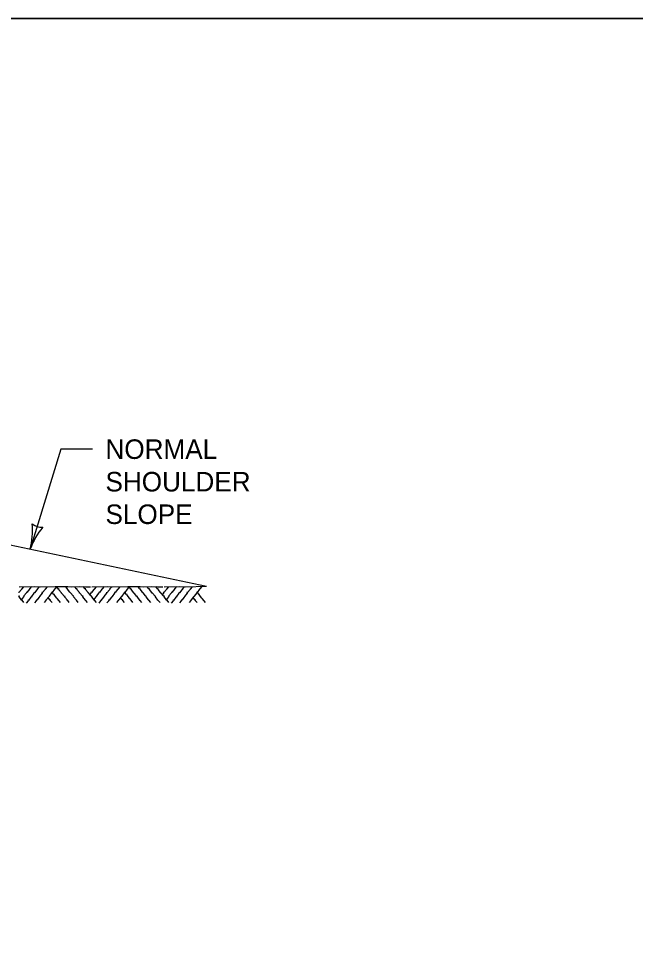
# Model space of a CAD drawing. Extents: x 49991.4 to 50021, y 49987.6 to 50011.4.
# Drawn here: x 50006.771 to 50008.666, y 49996.145 to 49998.999 of the extents above; entities that cross this region are included whole.
import ezdxf

# ---------------------------------------------------------------- set-up
doc = ezdxf.new("R2010")
doc.units = 0
for name, color, linetype in [('Level 1', 7, 'Continuous'), ('Level 2', 7, 'Continuous'), ('Level 3', 7, 'Continuous'), ('Level 4', 7, 'Continuous')]:
    doc.layers.add(name, color=color, linetype=linetype)

msp = doc.modelspace()

# ---------------------------------------------------------------- linework, layer by layer
at = {"layer": 'Level 1'}
msp.add_lwpolyline([(49999.3835, 49998.9992), (50016.7501, 49998.9992), (50016.7501, 49987.7988), (49999.3835, 49987.7988)], close=True, dxfattribs=at)
for points in [[(50006.7866, 49997.2531), (50006.7806, 49997.246), (50006.7814, 49997.2445), (50006.7799, 49997.2445), (50006.7724, 49997.2351), (50006.7715, 49997.2351)], [(50006.7736, 49997.2526), (50006.8206, 49997.2545), (50006.8384, 49997.2526), (50006.884, 49997.2541), (50006.9224, 49997.2543), (50006.933, 49997.2529), (50006.9581, 49997.2545), (50006.9773, 49997.2535), (50006.992, 49997.2526)], [(50006.8112, 49997.2543), (50006.8052, 49997.2471), (50006.806, 49997.2455), (50006.8045, 49997.2455), (50006.7972, 49997.2361), (50006.795, 49997.2361), (50006.7955, 49997.2345), (50006.7877, 49997.2249), (50006.7877, 49997.2229), (50006.786, 49997.2225), (50006.78, 49997.2145)], [(50006.8338, 49997.2525), (50006.8282, 49997.2459), (50006.8288, 49997.2443), (50006.8276, 49997.2443), (50006.8201, 49997.2349), (50006.8182, 49997.2349), (50006.8183, 49997.2331), (50006.8106, 49997.2235), (50006.8106, 49997.2215), (50006.8092, 49997.2211), (50006.8018, 49997.2115), (50006.8, 49997.2115), (50006.8003, 49997.2095), (50006.795, 49997.2033)], [(50006.8594, 49997.2533), (50006.8534, 49997.246), (50006.8542, 49997.2445), (50006.8526, 49997.2445), (50006.8453, 49997.2351), (50006.8432, 49997.2351), (50006.8436, 49997.2333), (50006.836, 49997.2237), (50006.836, 49997.222), (50006.8342, 49997.2213), (50006.827, 49997.2119), (50006.825, 49997.2117), (50006.8255, 49997.21), (50006.8202, 49997.2034)], [(50006.8888, 49997.2541), (50006.8828, 49997.2469), (50006.8836, 49997.2454), (50006.8822, 49997.2454), (50006.8747, 49997.2361), (50006.8729, 49997.2361), (50006.873, 49997.2341), (50006.8654, 49997.2245), (50006.8654, 49997.2229), (50006.8638, 49997.2221), (50006.8564, 49997.2129), (50006.8548, 49997.2125), (50006.855, 49997.2109), (50006.8498, 49997.2045)], [(50006.9272, 49997.2045), (50006.9224, 49997.2107), (50006.9209, 49997.2105), (50006.9212, 49997.2119), (50006.9136, 49997.2211), (50006.9142, 49997.2231), (50006.9122, 49997.2231), (50006.9047, 49997.2329), (50006.903, 49997.2333), (50006.9028, 49997.2349), (50006.8952, 49997.2443), (50006.8956, 49997.246), (50006.8938, 49997.2461), (50006.8886, 49997.2527)], [(50006.9546, 49997.2049), (50006.9491, 49997.2123), (50006.9473, 49997.2119), (50006.9478, 49997.2135), (50006.9402, 49997.2227), (50006.9406, 49997.2245), (50006.9389, 49997.2249), (50006.9312, 49997.2345), (50006.9296, 49997.2347), (50006.9293, 49997.2365), (50006.9218, 49997.2459), (50006.9221, 49997.2477), (50006.9202, 49997.2477), (50006.915, 49997.2543)], [(50006.9833, 49997.2045), (50006.9778, 49997.2115), (50006.9762, 49997.2113), (50006.9766, 49997.2125), (50006.969, 49997.222), (50006.9695, 49997.2239), (50006.9676, 49997.2241), (50006.96, 49997.2335), (50006.9584, 49997.234), (50006.9581, 49997.2359), (50006.9506, 49997.2451), (50006.9509, 49997.2469), (50006.9491, 49997.2469), (50006.944, 49997.2535)], [(50006.9938, 49997.2249), (50006.9868, 49997.2339), (50006.9851, 49997.2341), (50006.9848, 49997.2359), (50006.9772, 49997.2453), (50006.9776, 49997.2471), (50006.9756, 49997.2471), (50006.9702, 49997.2539)], [(50007.0094, 49997.2531), (50007.0034, 49997.246), (50007.0042, 49997.2445), (50007.0026, 49997.2445), (50006.9952, 49997.2351), (50006.9942, 49997.2351)], [(50006.996, 49997.2526), (50007.0433, 49997.2545), (50007.0612, 49997.2526), (50007.1068, 49997.2541), (50007.1452, 49997.2543), (50007.1558, 49997.2529), (50007.1807, 49997.2545), (50007.2, 49997.2535), (50007.2148, 49997.2526)], [(50007.034, 49997.2543), (50007.028, 49997.2471), (50007.0288, 49997.2455), (50007.0272, 49997.2455), (50007.0199, 49997.2361), (50007.0178, 49997.2361), (50007.0182, 49997.2345), (50007.0106, 49997.2249), (50007.0106, 49997.2229), (50007.0088, 49997.2225), (50007.0028, 49997.2145)], [(50007.0565, 49997.2525), (50007.0511, 49997.2459), (50007.0517, 49997.2443), (50007.0502, 49997.2443), (50007.0427, 49997.2349), (50007.0409, 49997.2349), (50007.041, 49997.2331), (50007.0334, 49997.2235), (50007.0334, 49997.2215), (50007.0319, 49997.2211), (50007.0244, 49997.2115), (50007.0228, 49997.2115), (50007.023, 49997.2095), (50007.0178, 49997.2033)], [(50007.0822, 49997.2533), (50007.0762, 49997.246), (50007.0769, 49997.2445), (50007.0754, 49997.2445), (50007.068, 49997.2351), (50007.0661, 49997.2351), (50007.0664, 49997.2333), (50007.0588, 49997.2237), (50007.0588, 49997.222), (50007.0571, 49997.2213), (50007.0498, 49997.2119), (50007.0478, 49997.2117), (50007.0482, 49997.21), (50007.043, 49997.2034)], [(50007.1116, 49997.2541), (50007.1057, 49997.2469), (50007.1063, 49997.2454), (50007.1051, 49997.2454), (50007.0976, 49997.2361), (50007.0956, 49997.2361), (50007.0958, 49997.2341), (50007.0882, 49997.2245), (50007.0882, 49997.2229), (50007.0865, 49997.2221), (50007.0792, 49997.2129), (50007.0775, 49997.2125), (50007.0778, 49997.2109), (50007.0726, 49997.2045)], [(50007.1501, 49997.2045), (50007.1452, 49997.2107), (50007.1436, 49997.2105), (50007.1441, 49997.2119), (50007.1366, 49997.2211), (50007.1369, 49997.2231), (50007.1351, 49997.2231), (50007.1276, 49997.2329), (50007.1256, 49997.2333), (50007.1255, 49997.2349), (50007.118, 49997.2443), (50007.1182, 49997.246), (50007.1165, 49997.2461), (50007.1114, 49997.2527)], [(50007.1774, 49997.2049), (50007.1717, 49997.2123), (50007.17, 49997.2119), (50007.1705, 49997.2135), (50007.163, 49997.2227), (50007.1633, 49997.2245), (50007.1616, 49997.2249), (50007.154, 49997.2345), (50007.1522, 49997.2347), (50007.152, 49997.2365), (50007.1444, 49997.2459), (50007.1447, 49997.2477), (50007.1429, 49997.2477), (50007.1378, 49997.2543)], [(50007.206, 49997.2045), (50007.2005, 49997.2115), (50007.199, 49997.2113), (50007.1993, 49997.2125), (50007.1918, 49997.222), (50007.1922, 49997.2239), (50007.1906, 49997.2241), (50007.1828, 49997.2335), (50007.1812, 49997.234), (50007.1807, 49997.2359), (50007.1732, 49997.2451), (50007.1736, 49997.2469), (50007.1717, 49997.2469), (50007.1668, 49997.2535)], [(50007.2166, 49997.2249), (50007.2095, 49997.2339), (50007.2077, 49997.2341), (50007.2076, 49997.2359), (50007.1999, 49997.2453), (50007.2002, 49997.2471), (50007.1984, 49997.2471), (50007.1932, 49997.2539)], [(50007.2322, 49997.2531), (50007.2262, 49997.246), (50007.2269, 49997.2445), (50007.2254, 49997.2445), (50007.2179, 49997.2351), (50007.217, 49997.2351)], [(50007.2188, 49997.2526), (50007.266, 49997.2545), (50007.2839, 49997.2526), (50007.3483, 49997.2547)], [(50007.2568, 49997.2543), (50007.2508, 49997.2471), (50007.2515, 49997.2455), (50007.25, 49997.2455), (50007.2426, 49997.2361), (50007.2406, 49997.2361), (50007.241, 49997.2345), (50007.2332, 49997.2249), (50007.2332, 49997.2229), (50007.2316, 49997.2225), (50007.2256, 49997.2145)], [(50007.2792, 49997.2525), (50007.2737, 49997.2459), (50007.2746, 49997.2443), (50007.2731, 49997.2443), (50007.2656, 49997.2349), (50007.2636, 49997.2349), (50007.2638, 49997.2331), (50007.2562, 49997.2235), (50007.2562, 49997.2215), (50007.2546, 49997.2211), (50007.2473, 49997.2115), (50007.2455, 49997.2115), (50007.2458, 49997.2095), (50007.2406, 49997.2033)], [(50007.3049, 49997.2533), (50007.2989, 49997.246), (50007.2996, 49997.2445), (50007.2982, 49997.2445), (50007.2906, 49997.2351), (50007.2887, 49997.2351), (50007.2892, 49997.2333), (50007.2815, 49997.2237), (50007.2815, 49997.222), (50007.2797, 49997.2213), (50007.2725, 49997.2119), (50007.2706, 49997.2117), (50007.271, 49997.21), (50007.2658, 49997.2034)], [(50007.3343, 49997.2541), (50007.3286, 49997.2469), (50007.329, 49997.2454), (50007.3277, 49997.2454), (50007.3202, 49997.2361), (50007.3184, 49997.2361), (50007.3186, 49997.2341), (50007.3109, 49997.2245), (50007.3109, 49997.2229), (50007.3092, 49997.2221), (50007.302, 49997.2129), (50007.3002, 49997.2125), (50007.3006, 49997.2109), (50007.2953, 49997.2045)], [(50006.7876, 49997.2046), (50006.7822, 49997.2117), (50006.7805, 49997.2113), (50006.7808, 49997.2129), (50006.7733, 49997.2221), (50006.7738, 49997.2241), (50006.7721, 49997.2243), (50006.7715, 49997.2249)], [(50006.8742, 49997.2047), (50006.8687, 49997.2115), (50006.869, 49997.2131), (50006.867, 49997.2135), (50006.8621, 49997.2199)], [(50006.8998, 49997.2053), (50006.891, 49997.2161), (50006.8894, 49997.2166), (50006.8892, 49997.2184), (50006.8818, 49997.2275), (50006.8819, 49997.2295), (50006.8801, 49997.2295), (50006.875, 49997.2359)], [(50006.9941, 49997.2351), (50006.993, 49997.2351), (50006.9935, 49997.2333), (50006.9905, 49997.2297)], [(50007.0103, 49997.2046), (50007.0049, 49997.2117), (50007.0034, 49997.2113), (50007.0036, 49997.2129), (50006.996, 49997.2221), (50006.9965, 49997.2241), (50006.9947, 49997.2243), (50006.9942, 49997.2249)], [(50007.0967, 49997.2047), (50007.0916, 49997.2115), (50007.0918, 49997.2131), (50007.0898, 49997.2135), (50007.0847, 49997.2199)], [(50007.1225, 49997.2053), (50007.1138, 49997.2161), (50007.1122, 49997.2166), (50007.112, 49997.2184), (50007.1045, 49997.2275), (50007.1046, 49997.2295), (50007.1027, 49997.2295), (50007.0979, 49997.2359)], [(50007.2167, 49997.2351), (50007.2158, 49997.2351), (50007.2162, 49997.2333), (50007.2132, 49997.2297)], [(50007.233, 49997.2046), (50007.2276, 49997.2117), (50007.2262, 49997.2113), (50007.2263, 49997.2129), (50007.2188, 49997.2221), (50007.2192, 49997.2241), (50007.2176, 49997.2243), (50007.217, 49997.2249)], [(50007.3196, 49997.2047), (50007.3142, 49997.2115), (50007.3145, 49997.2131), (50007.3127, 49997.2135), (50007.3076, 49997.2199)], [(50007.3452, 49997.2053), (50007.3366, 49997.2161), (50007.3349, 49997.2166), (50007.3348, 49997.2184), (50007.3272, 49997.2275), (50007.3274, 49997.2295), (50007.3258, 49997.2295), (50007.3206, 49997.2359)]]:
    msp.add_lwpolyline(points, dxfattribs=at)
at = {"layer": 'Level 2'}
msp.add_line((50016.7501, 49998.9992), (49999.3835, 49998.9992), dxfattribs=at)
at = {"layer": 'Level 3'}
for p, q in [((50006.9016, 49997.6761), (50006.8071, 49997.3685)), ((50006.9983, 49997.6761), (50006.9016, 49997.6761))]:
    msp.add_line(p, q, dxfattribs=at)
for centre, radius, start, end in [((50006.5813, 49997.4258), 0.233, 345.7574, 5.0072), ((50007.0168, 49997.2946), 0.2223, 140.3861, 160.5696), ((50006.8448, 49997.4911), 0.0548, 235.0689, 270.7912)]:
    msp.add_arc(centre, radius, start, end, dxfattribs=at)
at = {"layer": 'Level 4'}
msp.add_line((50005.9442, 49997.55), (50007.3483, 49997.2547), dxfattribs=at)

# ---------------------------------------------------------------- texts
at = {"layer": 'Level 2'}
for s, p in [('NORMAL', (50007.0383, 49997.6461)), ('SHOULDER', (50007.0383, 49997.5461)), ('SLOPE', (50007.0383, 49997.4461))]:
    msp.add_text(s, height=0.06, dxfattribs=at).set_placement(p)

doc.saveas('drawing.dxf')
